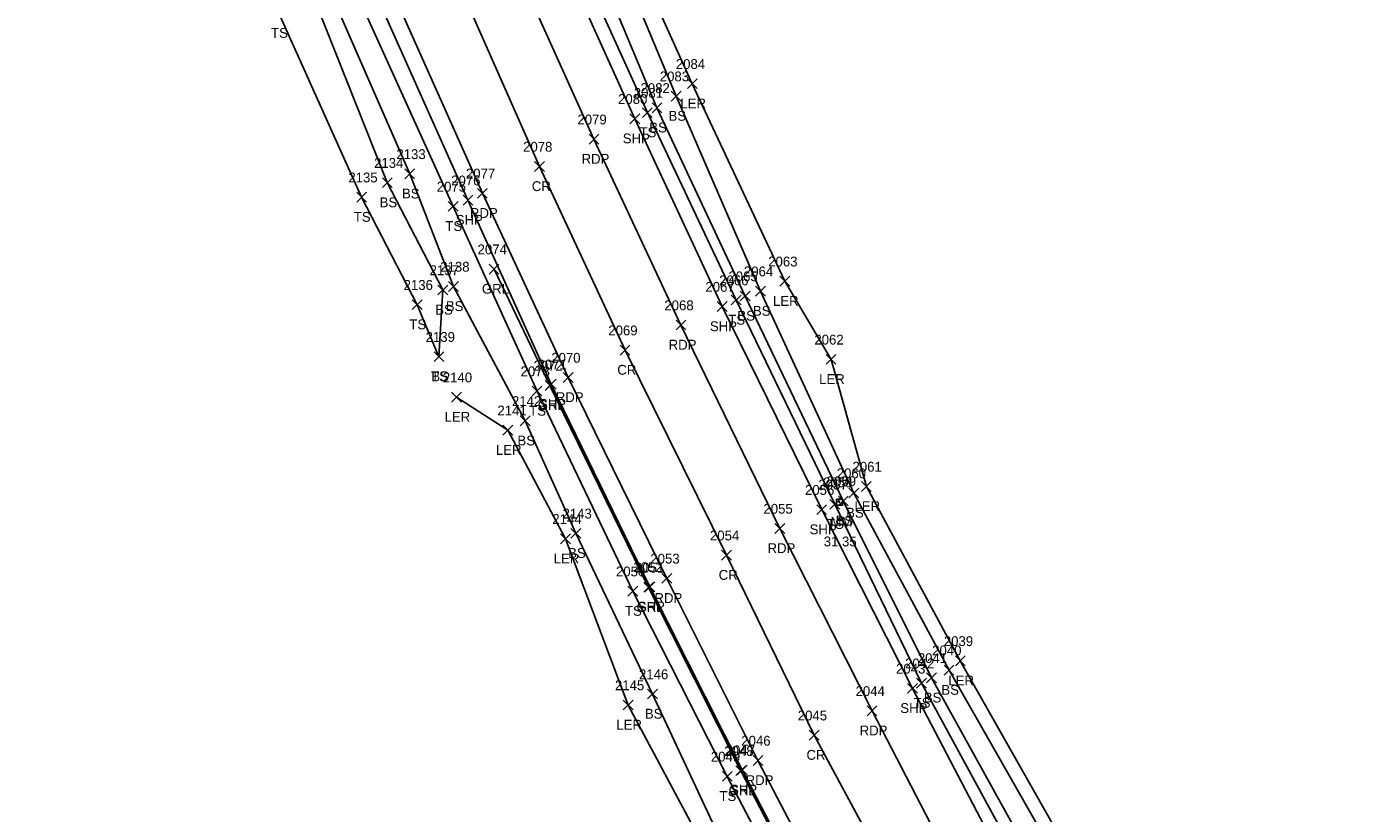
# Model space of a CAD drawing. Extents: x 1647574 to 1652703, y 212895 to 228670.
# Drawn here: x 1647845.9 to 1648116.3, y 228351 to 228510.8 of the extents above; entities that cross this region are included whole.
import ezdxf

# ---------------------------------------------------------------- set-up
doc = ezdxf.new("R2010")
doc.units = 0
for name, color, linetype in [('L_A', 7, 'Continuous'), ('L_I', 7, 'Continuous'), ('L_TIC', 7, 'Continuous'), ('LARO', 7, 'Continuous'), ('LELB', 7, 'Continuous'), ('P_A', 7, 'Continuous'), ('P_I', 7, 'Continuous'), ('P_TIC', 7, 'Continuous'), ('PET', 7, 'Continuous'), ('PRC', 7, 'Continuous'), ('PSP', 7, 'Continuous'), ('R_A', 7, 'Continuous'), ('R_I', 7, 'Continuous'), ('R_TIC', 7, 'Continuous'), ('RGR', 7, 'Continuous'), ('S_A', 7, 'Continuous'), ('S_C', 7, 'Continuous'), ('S_I', 7, 'Continuous'), ('SRM', 7, 'Continuous')]:
    doc.layers.add(name, color=color, linetype=linetype)

msp = doc.modelspace()

# ---------------------------------------------------------------- linework, layer by layer
at = {"layer": 'L_TIC'}
for points in [[(1647980.12, 228498.17), (1647982.12, 228500.17)], [(1647982.12, 228498.17), (1647980.12, 228500.17)], [(1647976.86, 228495.65), (1647978.86, 228497.65)], [(1647978.86, 228495.65), (1647976.86, 228497.65)], [(1647971, 228492.31), (1647973, 228494.31)], [(1647973, 228492.31), (1647971, 228494.31)], [(1647972.95, 228493.28), (1647974.95, 228495.28)], [(1647974.95, 228493.28), (1647972.95, 228495.28)], [(1647922.71, 228479.87), (1647924.71, 228481.87)], [(1647924.71, 228479.87), (1647922.71, 228481.87)], [(1647918.16, 228478.08), (1647920.16, 228480.08)], [(1647920.16, 228478.08), (1647918.16, 228480.08)], [(1647912.95, 228475.13), (1647914.95, 228477.13)], [(1647914.95, 228475.13), (1647912.95, 228477.13)], [(1647931.55, 228473.27), (1647933.55, 228475.27)], [(1647933.55, 228473.27), (1647931.55, 228475.27)], [(1647931.61, 228457), (1647933.61, 228459)], [(1647933.61, 228457), (1647931.61, 228459)], [(1647998.94, 228458.06), (1648000.94, 228460.06)], [(1648000.94, 228458.06), (1647998.94, 228460.06)], [(1647929.46, 228456.29), (1647931.46, 228458.29)], [(1647931.46, 228456.29), (1647929.46, 228458.29)], [(1647989.03, 228454.24), (1647991.03, 228456.24)], [(1647991.03, 228454.24), (1647989.03, 228456.24)], [(1647990.85, 228455.05), (1647992.85, 228457.05)], [(1647992.85, 228455.05), (1647990.85, 228457.05)], [(1647994, 228456.05), (1647996, 228458.05)], [(1647996, 228456.05), (1647994, 228458.05)], [(1647924.23, 228453.3), (1647926.23, 228455.3)], [(1647926.23, 228453.3), (1647924.23, 228455.3)], [(1647928.66, 228442.74), (1647930.66, 228444.74)], [(1647930.66, 228442.74), (1647928.66, 228444.74)], [(1647928.66, 228442.74), (1647930.66, 228444.74)], [(1647930.66, 228442.74), (1647928.66, 228444.74)], [(1648008.32, 228442.2), (1648010.32, 228444.2)], [(1648010.32, 228442.2), (1648008.32, 228444.2)], [(1647948.58, 228435.76), (1647950.58, 228437.76)], [(1647950.58, 228435.76), (1647948.58, 228437.76)], [(1647932.22, 228434.52), (1647934.22, 228436.52)], [(1647934.22, 228434.52), (1647932.22, 228436.52)], [(1647946.17, 228429.71), (1647948.17, 228431.71)], [(1647948.17, 228429.71), (1647946.17, 228431.71)], [(1647942.65, 228427.8), (1647944.65, 228429.8)], [(1647944.65, 228427.8), (1647942.65, 228429.8)], [(1648015.5, 228416.39), (1648017.5, 228418.39)], [(1648017.5, 228416.39), (1648015.5, 228418.39)], [(1648012.94, 228415.05), (1648014.94, 228417.05)], [(1648014.94, 228415.05), (1648012.94, 228417.05)], [(1648009.08, 228412.76), (1648011.08, 228414.76)], [(1648011.08, 228412.76), (1648009.08, 228414.76)], [(1648010.8, 228413.44), (1648012.8, 228415.44)], [(1648012.8, 228413.44), (1648010.8, 228415.44)], [(1647954.38, 228405.75), (1647956.38, 228407.75)], [(1647956.38, 228405.75), (1647954.38, 228407.75)], [(1647956.46, 228406.87), (1647958.46, 228408.87)], [(1647958.46, 228406.87), (1647956.46, 228408.87)], [(1647968.05, 228395.12), (1647970.05, 228397.12)], [(1647970.05, 228395.12), (1647968.05, 228397.12)], [(1648032.29, 228379.08), (1648034.29, 228381.08)], [(1648034.29, 228379.08), (1648032.29, 228381.08)], [(1648034.58, 228380.97), (1648036.58, 228382.97)], [(1648036.58, 228380.97), (1648034.58, 228382.97)], [(1648026.69, 228376.44), (1648028.69, 228378.44)], [(1648028.69, 228376.44), (1648026.69, 228378.44)], [(1648028.72, 228377.51), (1648030.72, 228379.51)], [(1648030.72, 228377.51), (1648028.72, 228379.51)], [(1647972.05, 228374.23), (1647974.05, 228376.23)], [(1647974.05, 228374.23), (1647972.05, 228376.23)], [(1647967.1, 228372), (1647969.1, 228374)], [(1647969.1, 228372), (1647967.1, 228374)], [(1647987.24, 228357.51), (1647989.24, 228359.51)], [(1647989.24, 228357.51), (1647987.24, 228359.51)]]:
    msp.add_lwpolyline(points, dxfattribs=at)
at = {"layer": 'LARO'}
for points in [[(1648079.64, 228304.78), (1648056.82, 228344.46), (1648035.58, 228381.97), (1648016.5, 228417.39), (1648009.32, 228443.2), (1647999.94, 228459.06), (1647981.12, 228499.17), (1647963.3, 228538.65)], [(1647933.22, 228435.52), (1647943.65, 228428.8), (1647955.38, 228406.75), (1647968.1, 228373), (1647987.18, 228337.23), (1648003.3, 228303.1)]]:
    msp.add_lwpolyline(points, dxfattribs=at)
at = {"layer": 'LELB'}
for points in [[(1648354.19, 227879.71), (1648321.73, 227919.78), (1648297.18, 227952.21), (1648269.36, 227989.06), (1648243.48, 228024.19), (1648219.28, 228058.75), (1648195.05, 228094.29), (1648173.04, 228128.05), (1648150.23, 228163.27), (1648127.62, 228199.76), (1648103.9, 228239.37), (1648088.91, 228265.67), (1648069.89, 228299.68), (1648049.11, 228338.12), (1648027.69, 228377.44), (1648010.08, 228413.76), (1647990.03, 228455.24), (1647972, 228493.31), (1647952.94, 228535.44), (1647937.18, 228575.23), (1647922.81, 228609.12), (1647903.55, 228659.1)], [(1648351.84, 227812.3), (1648319.03, 227851.85), (1648287.09, 227892.13), (1648260.82, 227925.49), (1648232.83, 227963.62), (1648207.81, 227997.28), (1648182.57, 228032.91), (1648159.55, 228068.16), (1648135.13, 228103.7), (1648112.63, 228139.57), (1648088.44, 228176.61), (1648065.81, 228216.55), (1648048.77, 228244.34), (1648030.34, 228278.62), (1648010.32, 228316.28), (1647988.24, 228358.51), (1647969.05, 228396.12), (1647949.58, 228436.76), (1647932.55, 228474.27), (1647912.45, 228518.68), (1647893.94, 228561.09), (1647881.68, 228593.27), (1647863.51, 228642.93)], [(1647856.99, 228640.62), (1647873.68, 228599.56), (1647891.2, 228556.85), (1647907.52, 228517.9), (1647923.71, 228480.87), (1647932.61, 228458), (1647947.17, 228430.71), (1647957.46, 228407.87), (1647973.05, 228375.23), (1647990.12, 228338.71), (1648007.66, 228306.18), (1648026.86, 228269.73), (1648050.03, 228227.83), (1648068.63, 228195.13), (1648090.12, 228158.96), (1648103.63, 228129.11), (1648111.3, 228097.1)], [(1647854.94, 228639.46), (1647868.55, 228597.62), (1647887.62, 228555.01), (1647904.47, 228516.05), (1647919.16, 228479.08), (1647930.46, 228457.29), (1647929.66, 228443.74)], [(1647845.88, 228634.73), (1647862.38, 228595.15), (1647880.87, 228551.33), (1647897.13, 228513.49), (1647913.95, 228476.13), (1647925.23, 228454.3), (1647929.66, 228443.74)], [(1648187.85, 228134.14), (1648161.26, 228169.32), (1648135.31, 228208.01), (1648112.05, 228244.65), (1648095.88, 228270.18), (1648077.48, 228303.1), (1648054.77, 228342.44), (1648033.29, 228380.08), (1648013.94, 228416.05), (1647995, 228457.05), (1647977.86, 228496.65), (1647960.38, 228538.51), (1647958.42, 228580.05)], [(1648199.35, 228096.72), (1648181.76, 228131.34), (1648157.62, 228167.73), (1648133.38, 228206.23), (1648109.51, 228242.64), (1648092.98, 228267.74), (1648072.08, 228300.5), (1648051.47, 228339.28), (1648029.72, 228378.51), (1648011.8, 228414.44), (1647991.85, 228456.05), (1647973.95, 228494.28), (1647956.36, 228536.31), (1647948.75, 228577.26)]]:
    msp.add_lwpolyline(points, dxfattribs=at)
at = {"layer": 'P_TIC'}
for points in [[(1647968.46, 228491.06), (1647970.46, 228493.06)], [(1647970.46, 228491.06), (1647968.46, 228493.06)], [(1647960.14, 228486.91), (1647962.14, 228488.91)], [(1647962.14, 228486.91), (1647960.14, 228488.91)], [(1647949.09, 228481.37), (1647951.09, 228483.37)], [(1647951.09, 228481.37), (1647949.09, 228483.37)], [(1647937.47, 228475.92), (1647939.47, 228477.92)], [(1647939.47, 228475.92), (1647937.47, 228477.92)], [(1647934.54, 228474.52), (1647936.54, 228476.52)], [(1647936.54, 228474.52), (1647934.54, 228476.52)], [(1647986.18, 228452.92), (1647988.18, 228454.92)], [(1647988.18, 228452.92), (1647986.18, 228454.92)], [(1647977.83, 228449.17), (1647979.83, 228451.17)], [(1647979.83, 228449.17), (1647977.83, 228451.17)], [(1647966.46, 228444.07), (1647968.46, 228446.07)], [(1647968.46, 228444.07), (1647966.46, 228446.07)], [(1647954.9, 228438.51), (1647956.9, 228440.51)], [(1647956.9, 228438.51), (1647954.9, 228440.51)], [(1647951.45, 228437.14), (1647953.45, 228439.14)], [(1647953.45, 228437.14), (1647951.45, 228439.14)], [(1648006.42, 228411.68), (1648008.42, 228413.68)], [(1648008.42, 228411.68), (1648006.42, 228413.68)], [(1647997.92, 228407.85), (1647999.92, 228409.85)], [(1647999.92, 228407.85), (1647997.92, 228409.85)], [(1647987.06, 228402.42), (1647989.06, 228404.42)], [(1647989.06, 228402.42), (1647987.06, 228404.42)], [(1647974.95, 228397.72), (1647976.95, 228399.72)], [(1647976.95, 228397.72), (1647974.95, 228399.72)], [(1647971.51, 228395.99), (1647973.51, 228397.99)], [(1647973.51, 228395.99), (1647971.51, 228397.99)], [(1648024.86, 228375.38), (1648026.86, 228377.38)], [(1648026.86, 228375.38), (1648024.86, 228377.38)], [(1648016.64, 228370.82), (1648018.64, 228372.82)], [(1648018.64, 228370.82), (1648016.64, 228372.82)], [(1648004.9, 228365.87), (1648006.9, 228367.87)], [(1648006.9, 228365.87), (1648004.9, 228367.87)], [(1647993.47, 228360.74), (1647995.47, 228362.74)], [(1647995.47, 228360.74), (1647993.47, 228362.74)], [(1647990.27, 228358.8), (1647992.27, 228360.8)], [(1647992.27, 228358.8), (1647990.27, 228360.8)]]:
    msp.add_lwpolyline(points, dxfattribs=at)
at = {"layer": 'PET'}
for points in [[(1648343.92, 227872.68), (1648312.18, 227912.42), (1648286.41, 227945.97), (1648259.83, 227981.4), (1648233.53, 228017.77), (1648209.68, 228051.59), (1648184.99, 228088.05), (1648163.33, 228121.58), (1648140.14, 228157.28), (1648117.89, 228193.29), (1648093.86, 228233.11), (1648077.72, 228260.65), (1648058.67, 228294.21), (1648038.3, 228331.93), (1648017.64, 228371.82), (1647998.92, 228408.85), (1647978.83, 228450.17), (1647961.14, 228487.91), (1647941.78, 228530.92), (1647924.27, 228572.85), (1647911.25, 228604.83), (1647891.72, 228655.58)], [(1648357.18, 227817.31), (1648324.35, 227856.66), (1648291.64, 227897.48), (1648266.75, 227930.03), (1648238.87, 227967.44), (1648213.55, 228002.24), (1648188.8, 228037.85), (1648165.1, 228072.75), (1648141.89, 228108.1), (1648118.76, 228143.77), (1648095.78, 228180.92), (1648072, 228220.25), (1648055.45, 228249.03), (1648036.53, 228282.02), (1648016.46, 228319.63), (1647994.47, 228361.74), (1647975.95, 228398.72), (1647955.9, 228439.51), (1647938.47, 228476.92), (1647918.59, 228521.53), (1647900.58, 228564.2), (1647887.86, 228595.77), (1647868.51, 228645.68)]]:
    msp.add_lwpolyline(points, dxfattribs=at)
at = {"layer": 'PRC'}
msp.add_lwpolyline([(1648367.06, 227824.4), (1648333.96, 227865.19), (1648301.98, 227905.03), (1648276.56, 227937.83), (1648249.38, 227974.31), (1648223.31, 228010.17), (1648199.56, 228044.67), (1648175.52, 228080.05), (1648153.19, 228113.7), (1648129.37, 228150.61), (1648107.24, 228186.18), (1648083.17, 228226.08), (1648067.05, 228254.73), (1648048.14, 228287.63), (1648028.02, 228325.77), (1648005.9, 228366.87), (1647988.06, 228403.42), (1647967.46, 228445.07), (1647950.09, 228482.37), (1647930.63, 228526.36), (1647912.39, 228569.25), (1647899.83, 228600.2), (1647880.56, 228650.37)], dxfattribs=at)
at = {"layer": 'PSP'}
for points in [[(1648352.03, 227878.52), (1648319.68, 227918.25), (1648294.86, 227950.71), (1648267.61, 227987.28), (1648241.44, 228023.36), (1648217.73, 228057.32), (1648192.95, 228093.18), (1648170.97, 228126.69), (1648148.28, 228162.02), (1648125.62, 228198.28), (1648101.68, 228238.38), (1648086.46, 228264.28), (1648067.22, 228298.38), (1648046.56, 228336.73), (1648025.86, 228376.38), (1648007.42, 228412.68), (1647987.18, 228453.92), (1647969.46, 228492.06), (1647950.16, 228534.75), (1647933.77, 228574.46), (1647920.08, 228608.39), (1647900.95, 228658.43)], [(1648354.02, 227814.19), (1648321.06, 227853.92), (1648288.58, 227894.46), (1648263.39, 227927.38), (1648235.52, 227964.75), (1648210.1, 227999.58), (1648185.31, 228035.32), (1648161.26, 228070.47), (1648138.25, 228105.61), (1648115.28, 228141.45), (1648092.15, 228178.84), (1648068.52, 228217.79), (1648052.14, 228246.38), (1648033.46, 228279.87), (1648013.32, 228317.27), (1647991.27, 228359.8), (1647972.51, 228396.99), (1647952.45, 228438.14), (1647935.54, 228475.52), (1647915.56, 228520.25), (1647897.47, 228562.77), (1647884.83, 228594.37), (1647865.74, 228644.27)]]:
    msp.add_lwpolyline(points, dxfattribs=at)
at = {"layer": 'R_TIC'}
for points in [[(1647939.84, 228460.53), (1647941.84, 228462.53)], [(1647941.84, 228460.53), (1647939.84, 228462.53)], [(1647951.2, 228436.9), (1647953.2, 228438.9)], [(1647953.2, 228436.9), (1647951.2, 228438.9)], [(1647971.26, 228395.89), (1647973.26, 228397.89)], [(1647973.26, 228395.89), (1647971.26, 228397.89)], [(1647989.97, 228358.65), (1647991.97, 228360.65)], [(1647991.97, 228358.65), (1647989.97, 228360.65)]]:
    msp.add_lwpolyline(points, dxfattribs=at)
at = {"layer": 'RGR'}
msp.add_lwpolyline([(1648353.62, 227813.75), (1648320.77, 227853.11), (1648288.36, 227894.15), (1648263.03, 227927.15), (1648235.12, 227964.21), (1648209.79, 227999.3), (1648184.57, 228034.7), (1648161.04, 228070.15), (1648137.99, 228105.47), (1648114.96, 228141.34), (1648091.9, 228178.37), (1648068.29, 228217.71), (1648051.79, 228246.29), (1648033.27, 228279.62), (1648013.01, 228317.2), (1647990.97, 228359.65), (1647972.26, 228396.89), (1647952.2, 228437.9), (1647940.84, 228461.53)], dxfattribs=at)
at = {"layer": 'SRM'}
msp.add_lwpolyline([(1648010.39, 228414.83), (1648011.64, 228414.83), (1648011.64, 228413.58), (1648010.39, 228413.58)], close=True, dxfattribs=at)
msp.add_circle((1648011.01, 228414.21), 0.0833, dxfattribs=at)

# ---------------------------------------------------------------- texts
at = {"layer": 'L_A'}
for s, p in [('TS', (1647895.54, 228508.49)), ('LER', (1647978.71, 228494.17)), ('BS', (1647972.39, 228489.28)), ('BS', (1647976.3, 228491.65)), ('TS', (1647970.41, 228488.31)), ('BS', (1647922.15, 228475.87)), ('BS', (1647917.6, 228474.08)), ('TS', (1647912.36, 228471.13)), ('TS', (1647930.96, 228469.27)), ('LER', (1647997.52, 228454.06)), ('BS', (1647928.9, 228452.29)), ('BS', (1647931.05, 228453)), ('BS', (1647993.44, 228452.05)), ('TS', (1647923.64, 228449.3)), ('TS', (1647988.44, 228450.24)), ('BS', (1647990.29, 228451.05)), ('TS', (1647928.06, 228438.74)), ('BS', (1647928.1, 228438.74)), ('LER', (1648006.9, 228438.2)), ('LER', (1647930.8, 228430.52)), ('TS', (1647947.99, 228431.76)), ('BS', (1647945.61, 228425.71)), ('LER', (1647941.23, 228423.8)), ('BS', (1648012.38, 228411.05)), ('LER', (1648014.08, 228412.39)), ('TS', (1648008.49, 228408.76)), ('BS', (1648010.24, 228409.44)), ('BS', (1647955.9, 228402.87)), ('LER', (1647952.96, 228401.75)), ('TS', (1647967.45, 228391.12)), ('LER', (1648033.16, 228376.97)), ('BS', (1648028.16, 228373.51)), ('BS', (1648031.73, 228375.08)), ('BS', (1647971.49, 228370.23)), ('TS', (1648026.1, 228372.44)), ('LER', (1647965.69, 228368)), ('TS', (1647986.65, 228353.51))]:
    msp.add_text(s, height=2, dxfattribs=at).set_placement(p)
at = {"layer": 'L_I'}
for s, p in [('2084', (1647977.78, 228502.17)), ('2082', (1647970.61, 228497.28)), ('2083', (1647974.52, 228499.65)), ('2081', (1647969.23, 228496.31)), ('2133', (1647921.01, 228483.87)), ('2134', (1647916.47, 228482.08)), ('2135', (1647911.25, 228479.13)), ('2075', (1647929.21, 228477.27)), ('2137', (1647927.76, 228460.29)), ('2138', (1647929.92, 228461)), ('2064', (1647991.61, 228460.05)), ('2063', (1647996.55, 228462.06)), ('2136', (1647922.48, 228457.3)), ('2066', (1647986.59, 228458.24)), ('2065', (1647988.46, 228459.05)), ('2139', (1647926.95, 228446.74)), ('2139', (1647926.95, 228446.74)), ('2062', (1648005.93, 228446.2)), ('2140', (1647930.44, 228438.52)), ('2073', (1647946.24, 228439.76)), ('2142', (1647944.48, 228433.71)), ('2141', (1647941.53, 228431.8)), ('2060', (1648010.47, 228419.05)), ('2061', (1648013.68, 228420.39)), ('2057', (1648006.74, 228416.76)), ('2059', (1648008.45, 228417.44)), ('2143', (1647954.76, 228410.87)), ('2144', (1647952.69, 228409.75)), ('2050', (1647965.62, 228399.12)), ('2039', (1648032.23, 228384.97)), ('2041', (1648026.95, 228381.51)), ('2040', (1648029.86, 228383.08)), ('2042', (1648024.35, 228380.44)), ('2145', (1647965.41, 228376)), ('2146', (1647970.3, 228378.23)), ('2049', (1647984.9, 228361.51))]:
    msp.add_text(s, height=2, dxfattribs=at).set_placement(p)
at = {"layer": 'P_A'}
for s, p in [('SHP', (1647967, 228487.06)), ('RDP', (1647958.63, 228482.91)), ('CR', (1647948.52, 228477.37)), ('SHP', (1647933.07, 228470.52)), ('RDP', (1647935.95, 228471.92)), ('SHP', (1647984.71, 228448.92)), ('RDP', (1647976.32, 228445.17)), ('CR', (1647965.89, 228440.07)), ('SHP', (1647949.98, 228433.14)), ('RDP', (1647953.39, 228434.51)), ('SHP', (1648004.96, 228407.68)), ('RDP', (1647996.41, 228403.85)), ('CR', (1647986.49, 228398.42)), ('SHP', (1647970.04, 228391.99)), ('RDP', (1647973.44, 228393.72)), ('SHP', (1648023.39, 228371.38)), ('RDP', (1648015.13, 228366.82)), ('CR', (1648004.33, 228361.87)), ('RDP', (1647991.96, 228356.74)), ('SHP', (1647988.8, 228354.8))]:
    msp.add_text(s, height=2, dxfattribs=at).set_placement(p)
at = {"layer": 'P_I'}
for s, p in [('2080', (1647966.04, 228495.06)), ('2079', (1647957.79, 228490.91)), ('2078', (1647946.75, 228485.37)), ('2076', (1647932.14, 228478.52)), ('2077', (1647935.13, 228479.92)), ('2067', (1647983.79, 228456.92)), ('2068', (1647975.45, 228453.17)), ('2069', (1647964.06, 228448.07)), ('2071', (1647949.67, 228441.14)), ('2070', (1647952.47, 228442.51)), ('2056', (1648004.03, 228415.68)), ('2055', (1647995.58, 228411.85)), ('2054', (1647984.72, 228406.42)), ('2052', (1647969.17, 228399.99)), ('2053', (1647972.61, 228401.72)), ('2043', (1648022.52, 228379.38)), ('2044', (1648014.3, 228374.82)), ('2045', (1648002.56, 228369.87)), ('2047', (1647987.93, 228362.8)), ('2046', (1647991.08, 228364.74))]:
    msp.add_text(s, height=2, dxfattribs=at).set_placement(p)
at = {"layer": 'R_A'}
for p in [(1647938.38, 228456.53), (1647949.74, 228432.9), (1647969.81, 228391.89), (1647988.51, 228354.65)]:
    msp.add_text('GRL', height=2, dxfattribs=at).set_placement(p)
at = {"layer": 'R_I'}
for s, p in [('2074', (1647937.5, 228464.53)), ('2072', (1647948.86, 228440.9)), ('2051', (1647969.49, 228399.89)), ('2048', (1647987.63, 228362.65))]:
    msp.add_text(s, height=2, dxfattribs=at).set_placement(p)
at = {"layer": 'S_A'}
msp.add_text('MM', height=2, dxfattribs=at).set_placement((1648009.2, 228409.21))
at = {"layer": 'S_C'}
msp.add_text('31.35', height=2, dxfattribs=at).set_placement((1648007.83, 228405.21))
at = {"layer": 'S_I'}
msp.add_text('2058', height=2, dxfattribs=at).set_placement((1648007.68, 228417.21))

doc.saveas('drawing.dxf')
